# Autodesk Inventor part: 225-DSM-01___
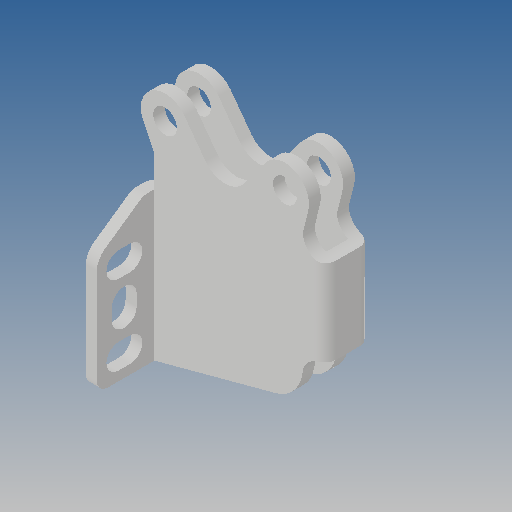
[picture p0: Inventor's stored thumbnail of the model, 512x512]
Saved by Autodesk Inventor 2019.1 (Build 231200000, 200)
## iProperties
Created: 2010-06
Part Number: 225-DSM-01___
Material: Ogólny
Document SubType Name: Modeling
Designer: CADENGINEERING4
Density: 1 g/cm^3
Appearance: Domyślna
Author: CADENGINEERING4
Revision Number: ANY
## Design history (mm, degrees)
feature "NONE"
node "Bryła1"
